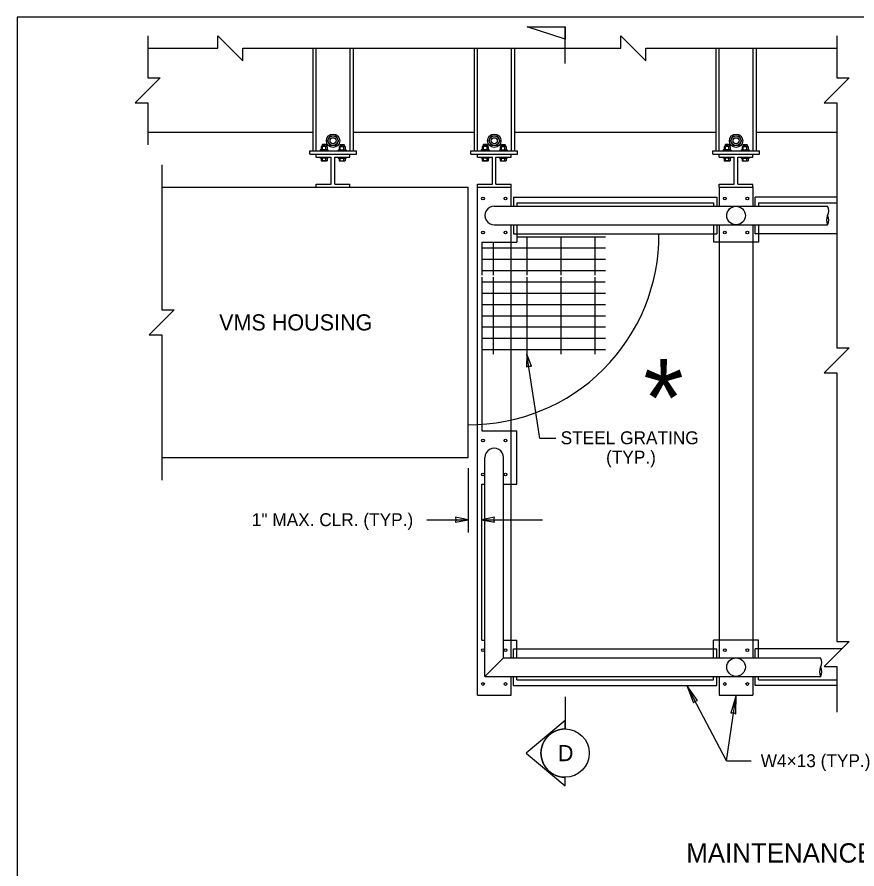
# Model space of a CAD drawing. Extents: x 99862 to 103151, y 100000 to 108076.
# Drawn here: x 99862 to 100904, y 107019 to 108076 of the extents above; entities that cross this region are included whole.
import ezdxf

# ---------------------------------------------------------------- set-up
doc = ezdxf.new("R2010")
doc.units = 0
for name, color, linetype in [('Level 1', 7, 'Continuous'), ('Level 15', 7, 'Continuous'), ('Level 2', 7, 'Continuous'), ('Level 20', 7, 'Continuous'), ('Level 4', 7, 'Continuous'), ('Level 5', 7, 'Continuous'), ('Level 6', 7, 'Continuous'), ('Level 9', 7, 'Continuous')]:
    doc.layers.add(name, color=color, linetype=linetype)

msp = doc.modelspace()

# ---------------------------------------------------------------- linework, layer by layer
at = {"layer": 'Level 1'}
msp.add_lwpolyline([(99862, 105999.5), (103151, 105999.5), (103151, 108075.5), (99862, 108075.5)], close=True, dxfattribs=at)
at = {"layer": 'Level 15'}
for p, q in [((100229.1, 108036.8), (100429.1, 108036.8)), ((100510.6, 107552.9), (100494.7, 107657.5)), ((100530.5, 107552.9), (100510.6, 107552.9)), ((100421.6, 107516), (100421.6, 107436.1)), ((100370.5, 107452.1), (100421.6, 107452.1)), ((100438.7, 107452.1), (100514.1, 107452.1)), ((100742.2, 107153.2), (100693.1, 107246.5)), ((100742.2, 107153.2), (100754.1, 107234.3)), ((100742.2, 107153.2), (100772.7, 107153.2))]:
    msp.add_line(p, q, dxfattribs=at)
for points in [[(100024.1, 108052.2), (100024.1, 108000.2), (100039.6, 108000.2), (100008.6, 107969.2), (100024.1, 107969.2), (100024.1, 107917.1)], [(100024.1, 108036.8), (100111.2, 108036.8), (100111.2, 108052.2), (100142.2, 108021.3), (100142.2, 108036.8), (100229.1, 108036.8)], [(100479.1, 108036.8), (100611, 108036.8), (100611, 108052.2), (100642, 108021.3), (100642, 108036.8), (100729.1, 108036.8)], [(100879.1, 108052.2), (100879.1, 108000.2), (100894.6, 108000.2), (100863.6, 107969.2), (100879.1, 107969.2), (100879.1, 107932.6)], [(100879.1, 107932.6), (100879.1, 107665.2), (100894.6, 107665.2), (100863.6, 107634.3), (100879.1, 107634.3), (100879.1, 107547.2)], [(100041.6, 107892.3), (100041.6, 107712.3), (100057.1, 107712.3), (100026.1, 107681.3), (100041.6, 107681.3), (100041.6, 107501.3)], [(100879.1, 107547.2), (100879.1, 107379.6)], [(100879.1, 107379.6), (100879.1, 107301), (100894.6, 107301), (100863.6, 107270), (100879.1, 107270), (100879.1, 107213.2)]]:
    msp.add_lwpolyline(points, dxfattribs=at)
for points in [[(100494.7, 107657.5), (100494, 107641.5), (100497, 107642.7), (100500.1, 107642.4)], [(100421.6, 107452.1), (100405.9, 107455.2), (100406.6, 107452.1), (100405.9, 107449)], [(100438.7, 107452.1), (100454.4, 107449), (100453.7, 107452.1), (100454.4, 107455.2)], [(100693.1, 107246.5), (100701.1, 107224.9), (100703.2, 107227.2), (100706.4, 107227.7)], [(100754.1, 107234.3), (100747.8, 107212.2), (100750.9, 107212.8), (100753.7, 107211.3)]]:
    msp.add_lwpolyline(points, close=True, dxfattribs=at)
for centre, start, end in [((100857.7, 107835.1), 330, 30), ((100877.7, 107823.5), 150, 210), ((100857.7, 107823.5), 330, 30), ((100849.1, 107275.1), 330, 30), ((100869.1, 107263.5), 150, 210), ((100849.1, 107263.5), 330, 30)]:
    msp.add_arc(centre, 11.5, start, end, dxfattribs=at)
at = {"layer": 'Level 2'}
for p, q in [((100229.1, 108036.8), (100229.1, 107909.6)), ((100229.1, 108036.8), (100279.1, 108036.8)), ((100279.1, 108036.8), (100279.1, 107909.6)), ((100429.1, 108036.8), (100429.1, 107909.6)), ((100429.1, 108036.8), (100479.1, 108036.8)), ((100479.1, 108036.8), (100479.1, 107909.6)), ((100729.1, 108036.8), (100729.1, 107909.6)), ((100729.1, 108036.8), (100879.1, 108036.8)), ((100779.1, 108036.8), (100779.1, 107909.6)), ((100024.1, 107932.6), (100229.1, 107932.6)), ((100279.1, 107932.6), (100429.1, 107932.6)), ((100479.1, 107932.6), (100729.1, 107932.6)), ((100779.1, 107932.6), (100879.1, 107932.6)), ((100225.1, 107909.6), (100283.1, 107909.6)), ((100225.1, 107905.6), (100225.1, 107909.6)), ((100283.1, 107905.6), (100283.1, 107909.6)), ((100425.1, 107909.6), (100483.1, 107909.6)), ((100425.1, 107905.6), (100425.1, 107909.6)), ((100483.1, 107905.6), (100483.1, 107909.6)), ((100725.1, 107909.6), (100783.1, 107909.6)), ((100725.1, 107905.6), (100725.1, 107909.6)), ((100783.1, 107905.6), (100783.1, 107909.6)), ((100225.1, 107905.6), (100283.1, 107905.6)), ((100233.1, 107901.6), (100233.1, 107905.6)), ((100233.1, 107901.6), (100251.9, 107901.6)), ((100251.9, 107868.3), (100251.9, 107901.6)), ((100256.1, 107901.6), (100275.1, 107901.6)), ((100256.1, 107868.3), (100256.1, 107901.6)), ((100275.1, 107901.6), (100275.1, 107905.6)), ((100425.1, 107905.6), (100483.1, 107905.6)), ((100433.1, 107901.6), (100433.1, 107905.6)), ((100433.1, 107901.6), (100452.1, 107901.6)), ((100451.9, 107868.3), (100451.9, 107901.6)), ((100456.1, 107901.6), (100475.1, 107901.6)), ((100456.1, 107868.3), (100456.1, 107901.6)), ((100475.1, 107901.6), (100475.1, 107905.6)), ((100725.1, 107905.6), (100783.1, 107905.6)), ((100733.1, 107901.6), (100733.1, 107905.6)), ((100733.1, 107901.6), (100752.1, 107901.6)), ((100751.9, 107868.3), (100751.9, 107901.6)), ((100756.1, 107901.6), (100775.1, 107901.6)), ((100756.1, 107868.3), (100756.1, 107901.6)), ((100775.1, 107901.6), (100775.1, 107905.6)), ((100233.1, 107864.3), (100233.1, 107868.3)), ((100233.1, 107868.3), (100251.9, 107868.3)), ((100256.1, 107868.3), (100275.1, 107868.3)), ((100275.1, 107864.3), (100275.1, 107868.3)), ((100433.1, 107864.3), (100433.1, 107868.3)), ((100433.1, 107868.3), (100451.9, 107868.3)), ((100456.1, 107868.3), (100475.1, 107868.3)), ((100475.1, 107864.3), (100475.1, 107868.3)), ((100733.1, 107864.3), (100733.1, 107868.3)), ((100733.1, 107868.3), (100751.9, 107868.3)), ((100756.1, 107868.3), (100775.1, 107868.3)), ((100775.1, 107864.3), (100775.1, 107868.3)), ((100041.6, 107864.3), (100421.6, 107864.3)), ((100233.1, 107864.3), (100275.1, 107864.3)), ((100421.6, 107529.3), (100421.6, 107864.3)), ((100433.1, 107864.3), (100475.1, 107864.3)), ((100733.1, 107864.3), (100775.1, 107864.3)), ((100041.6, 107529.3), (100421.6, 107529.3))]:
    msp.add_line(p, q, dxfattribs=at)
for points in [[(100233.1, 107909.6), (100233.1, 108036.8)], [(100275.1, 108036.8), (100275.1, 107909.6)], [(100433.1, 107909.6), (100433.1, 108036.8)], [(100475.1, 108036.8), (100475.1, 107909.6)], [(100733.1, 107909.6), (100733.1, 108036.8)], [(100775.1, 108036.8), (100775.1, 107909.6)]]:
    msp.add_lwpolyline(points, dxfattribs=at)
at = {"layer": 'Level 4'}
for p, q in [((100247.7, 107910.7), (100238, 107910.7)), ((100238, 107910.7), (100238, 107909.6)), ((100247.7, 107909.6), (100238, 107909.6)), ((100239.2, 107914.9), (100239.2, 107910.7)), ((100246.7, 107910.7), (100239.2, 107910.7)), ((100245.9, 107915.1), (100240, 107915.1)), ((100240.4, 107917.1), (100240.9, 107917.4)), ((100240.4, 107917.1), (100240.4, 107915.1)), ((100240.8, 107910.7), (100240.8, 107914.9)), ((100244.9, 107917.4), (100240.9, 107917.4)), ((100244.3, 107916.2), (100241.6, 107916.2)), ((100245.4, 107917.1), (100244.9, 107917.4)), ((100245.1, 107910.7), (100245.1, 107914.9)), ((100245.4, 107917.1), (100245.4, 107915.1)), ((100246.7, 107914.9), (100246.7, 107910.7)), ((100247.7, 107910.7), (100247.7, 107909.6)), ((100260.5, 107910.7), (100270.2, 107910.7)), ((100260.5, 107910.7), (100260.5, 107909.6)), ((100260.5, 107909.6), (100270.2, 107909.6)), ((100261.5, 107914.9), (100261.5, 107910.7)), ((100261.5, 107910.7), (100269, 107910.7)), ((100262.3, 107915.1), (100268.2, 107915.1)), ((100262.8, 107917.1), (100263.3, 107917.4)), ((100262.8, 107917.1), (100262.8, 107915.1)), ((100263.1, 107910.7), (100263.1, 107914.9)), ((100263.3, 107917.4), (100267.3, 107917.4)), ((100263.9, 107916.2), (100266.6, 107916.2)), ((100267.8, 107917.1), (100267.3, 107917.4)), ((100267.4, 107910.7), (100267.4, 107914.9)), ((100267.8, 107917.1), (100267.8, 107915.1)), ((100269, 107914.9), (100269, 107910.7)), ((100270.2, 107910.7), (100270.2, 107909.6)), ((100447.7, 107910.7), (100438, 107910.7)), ((100438, 107910.7), (100438, 107909.6)), ((100447.7, 107909.6), (100438, 107909.6)), ((100439.2, 107914.9), (100439.2, 107910.7)), ((100446.7, 107910.7), (100439.2, 107910.7)), ((100445.9, 107915.1), (100440, 107915.1)), ((100440.4, 107917.1), (100440.9, 107917.4)), ((100440.4, 107917.1), (100440.4, 107915.1)), ((100440.8, 107910.7), (100440.8, 107914.9)), ((100444.9, 107917.4), (100440.9, 107917.4)), ((100444.3, 107916.2), (100441.6, 107916.2)), ((100445.4, 107917.1), (100444.9, 107917.4)), ((100445.1, 107910.7), (100445.1, 107914.9)), ((100445.4, 107917.1), (100445.4, 107915.1)), ((100446.7, 107914.9), (100446.7, 107910.7)), ((100447.7, 107910.7), (100447.7, 107909.6)), ((100460.5, 107910.7), (100470.2, 107910.7)), ((100460.5, 107910.7), (100460.5, 107909.6)), ((100460.5, 107909.6), (100470.2, 107909.6)), ((100461.5, 107914.9), (100461.5, 107910.7)), ((100461.5, 107910.7), (100469, 107910.7)), ((100462.3, 107915.1), (100468.2, 107915.1)), ((100462.8, 107917.1), (100463.3, 107917.4)), ((100462.8, 107917.1), (100462.8, 107915.1)), ((100463.1, 107910.7), (100463.1, 107914.9)), ((100463.3, 107917.4), (100467.3, 107917.4)), ((100463.9, 107916.2), (100466.6, 107916.2)), ((100467.8, 107917.1), (100467.3, 107917.4)), ((100467.4, 107910.7), (100467.4, 107914.9)), ((100467.8, 107917.1), (100467.8, 107915.1)), ((100469, 107914.9), (100469, 107910.7)), ((100470.2, 107910.7), (100470.2, 107909.6)), ((100747.7, 107910.7), (100738, 107910.7)), ((100738, 107910.7), (100738, 107909.6)), ((100747.7, 107909.6), (100738, 107909.6)), ((100739.2, 107914.9), (100739.2, 107910.7)), ((100746.7, 107910.7), (100739.2, 107910.7)), ((100745.9, 107915.1), (100740, 107915.1)), ((100740.4, 107917.1), (100740.9, 107917.4)), ((100740.4, 107917.1), (100740.4, 107915.1)), ((100740.8, 107910.7), (100740.8, 107914.9)), ((100744.9, 107917.4), (100740.9, 107917.4)), ((100744.3, 107916.2), (100741.6, 107916.2)), ((100745.4, 107917.1), (100744.9, 107917.4)), ((100745.1, 107910.7), (100745.1, 107914.9)), ((100745.4, 107917.1), (100745.4, 107915.1)), ((100746.7, 107914.9), (100746.7, 107910.7)), ((100747.7, 107910.7), (100747.7, 107909.6)), ((100760.5, 107910.7), (100770.2, 107910.7)), ((100760.5, 107910.7), (100760.5, 107909.6)), ((100760.5, 107909.6), (100770.2, 107909.6)), ((100761.5, 107914.9), (100761.5, 107910.7)), ((100761.5, 107910.7), (100769, 107910.7)), ((100762.3, 107915.1), (100768.2, 107915.1)), ((100762.8, 107917.1), (100763.3, 107917.4)), ((100762.8, 107917.1), (100762.8, 107915.1)), ((100763.1, 107910.7), (100763.1, 107914.9)), ((100763.3, 107917.4), (100767.3, 107917.4)), ((100763.9, 107916.2), (100766.6, 107916.2)), ((100767.8, 107917.1), (100767.3, 107917.4)), ((100767.4, 107910.7), (100767.4, 107914.9)), ((100767.8, 107917.1), (100767.8, 107915.1)), ((100769, 107914.9), (100769, 107910.7)), ((100770.2, 107910.7), (100770.2, 107909.6)), ((100238, 107901.6), (100238, 107900.4)), ((100247.7, 107900.4), (100238, 107900.4)), ((100239.2, 107900.4), (100239.2, 107897.3)), ((100246.7, 107900.4), (100239.2, 107900.4)), ((100245.9, 107897.1), (100240, 107897.1)), ((100240.8, 107897.3), (100240.8, 107900.4)), ((100245.1, 107897.3), (100245.1, 107900.4)), ((100246.7, 107900.4), (100246.7, 107897.3)), ((100247.7, 107901.6), (100247.7, 107900.4)), ((100260.5, 107901.6), (100260.5, 107900.4)), ((100260.5, 107900.4), (100270.2, 107900.4)), ((100261.5, 107900.4), (100261.5, 107897.3)), ((100261.5, 107900.4), (100269, 107900.4)), ((100262.3, 107897.1), (100268.2, 107897.1)), ((100263.1, 107897.3), (100263.1, 107900.4)), ((100267.4, 107897.3), (100267.4, 107900.4)), ((100269, 107900.4), (100269, 107897.3)), ((100270.2, 107901.6), (100270.2, 107900.4)), ((100438, 107901.6), (100438, 107900.4)), ((100447.7, 107900.4), (100438, 107900.4)), ((100439.2, 107900.4), (100439.2, 107897.3)), ((100446.7, 107900.4), (100439.2, 107900.4)), ((100445.9, 107897.1), (100440, 107897.1)), ((100440.8, 107897.3), (100440.8, 107900.4)), ((100445.1, 107897.3), (100445.1, 107900.4)), ((100446.7, 107900.4), (100446.7, 107897.3)), ((100447.7, 107901.6), (100447.7, 107900.4)), ((100460.5, 107901.6), (100460.5, 107900.4)), ((100460.5, 107900.4), (100470.2, 107900.4)), ((100461.5, 107900.4), (100461.5, 107897.3)), ((100461.5, 107900.4), (100469, 107900.4)), ((100462.3, 107897.1), (100468.2, 107897.1)), ((100463.1, 107897.3), (100463.1, 107900.4)), ((100467.4, 107897.3), (100467.4, 107900.4)), ((100469, 107900.4), (100469, 107897.3)), ((100470.2, 107901.6), (100470.2, 107900.4)), ((100738, 107901.6), (100738, 107900.4)), ((100747.7, 107900.4), (100738, 107900.4)), ((100739.2, 107900.4), (100739.2, 107897.3)), ((100746.7, 107900.4), (100739.2, 107900.4)), ((100745.9, 107897.1), (100740, 107897.1)), ((100740.8, 107897.3), (100740.8, 107900.4)), ((100745.1, 107897.3), (100745.1, 107900.4)), ((100746.7, 107900.4), (100746.7, 107897.3)), ((100747.7, 107901.6), (100747.7, 107900.4)), ((100760.5, 107901.6), (100760.5, 107900.4)), ((100760.5, 107900.4), (100770.2, 107900.4)), ((100761.5, 107900.4), (100761.5, 107897.3)), ((100761.5, 107900.4), (100769, 107900.4)), ((100762.3, 107897.1), (100768.2, 107897.1)), ((100763.1, 107897.3), (100763.1, 107900.4)), ((100767.4, 107897.3), (100767.4, 107900.4)), ((100769, 107900.4), (100769, 107897.3)), ((100770.2, 107901.6), (100770.2, 107900.4)), ((100433.1, 107234.3), (100433.1, 107864.3)), ((100475.1, 107840.8), (100475.1, 107864.3)), ((100733.1, 107864.3), (100733.1, 107840.8)), ((100775.1, 107864.3), (100775.1, 107840.8)), ((100477.9, 107852.1), (100730.3, 107852.1)), ((100477.9, 107852.1), (100477.9, 107840.8)), ((100482.1, 107845.1), (100726.1, 107845.1)), ((100482.1, 107845.1), (100482.1, 107840.8)), ((100726.1, 107845.1), (100726.1, 107840.8)), ((100730.3, 107852.1), (100730.3, 107840.8)), ((100879.1, 107852.1), (100777.9, 107852.1)), ((100777.9, 107840.8), (100777.9, 107852.1)), ((100782.1, 107845.1), (100879.1, 107845.1)), ((100782.1, 107845.1), (100782.1, 107840.8)), ((100475.1, 107280.8), (100475.1, 107817.8)), ((100477.9, 107817.8), (100477.9, 107806.6)), ((100482.1, 107817.8), (100482.1, 107796.1)), ((100726.1, 107817.8), (100726.1, 107796.1)), ((100730.3, 107817.8), (100730.3, 107806.6)), ((100733.1, 107817.8), (100733.1, 107280.8)), ((100775.1, 107817.8), (100775.1, 107280.8)), ((100777.9, 107806.6), (100777.9, 107817.8)), ((100782.1, 107817.8), (100782.1, 107796.1)), ((100477.9, 107806.6), (100730.3, 107806.6)), ((100482.1, 107803.1), (100592.3, 107803.1)), ((100494.7, 107803.1), (100494.7, 107755.5)), ((100536.7, 107803.1), (100536.7, 107755.5)), ((100578.7, 107803.1), (100578.7, 107755.5)), ((100879.1, 107806.6), (100777.9, 107806.6)), ((100438.7, 107796.1), (100482.1, 107796.1)), ((100438.7, 107796.1), (100438.7, 107755.5)), ((100452.7, 107796.1), (100452.7, 107755.5)), ((100782.1, 107796.1), (100726.1, 107796.1)), ((100438.7, 107789.1), (100592.3, 107789.1)), ((100438.7, 107775.1), (100592.3, 107775.1)), ((100438.7, 107761.1), (100592.3, 107761.1)), ((100438.7, 107752.7), (100438.7, 107562.5)), ((100452.7, 107752.7), (100452.7, 107657.5)), ((100494.7, 107752.7), (100494.7, 107657.5)), ((100536.7, 107752.7), (100536.7, 107657.5)), ((100578.7, 107752.7), (100578.7, 107657.5)), ((100438.7, 107747.1), (100591.9, 107747.1)), ((100438.7, 107733.1), (100592.3, 107733.1)), ((100438.7, 107719.1), (100592.3, 107719.1)), ((100438.7, 107705.1), (100592.3, 107705.1)), ((100438.7, 107691.1), (100592.3, 107691.1)), ((100438.7, 107677.1), (100592.3, 107677.1)), ((100438.7, 107663.1), (100592.3, 107663.1)), ((100438.7, 107562.5), (100482.1, 107562.5)), ((100482.1, 107496.1), (100482.1, 107562.5)), ((100438.7, 107302.5), (100438.7, 107496.1)), ((100438.7, 107496.1), (100442.6, 107496.1)), ((100465.6, 107496.1), (100482.1, 107496.1)), ((100438.7, 107302.5), (100442.6, 107302.5)), ((100465.6, 107302.5), (100482.1, 107302.5)), ((100482.1, 107280.8), (100482.1, 107302.5)), ((100782.1, 107302.5), (100726.1, 107302.5)), ((100726.1, 107280.8), (100726.1, 107302.5)), ((100782.1, 107280.8), (100782.1, 107302.5)), ((100477.9, 107292.1), (100730.3, 107292.1)), ((100477.9, 107280.8), (100477.9, 107292.1)), ((100730.3, 107280.8), (100730.3, 107292.1)), ((100777.9, 107280.8), (100777.9, 107292.1)), ((100885.7, 107292.1), (100777.9, 107292.1)), ((100475.1, 107234.3), (100475.1, 107257.8)), ((100477.9, 107246.5), (100477.9, 107257.8)), ((100482.1, 107253.5), (100482.1, 107257.8)), ((100482.1, 107253.5), (100726.1, 107253.5)), ((100726.1, 107253.5), (100726.1, 107257.8)), ((100730.3, 107246.5), (100730.3, 107257.8)), ((100733.1, 107257.8), (100733.1, 107234.3)), ((100775.1, 107257.8), (100775.1, 107234.3)), ((100777.9, 107246.5), (100777.9, 107257.8)), ((100782.1, 107253.5), (100782.1, 107257.8)), ((100782.1, 107253.5), (100879.1, 107253.5)), ((100477.9, 107246.5), (100730.3, 107246.5)), ((100879.1, 107246.5), (100777.9, 107246.5)), ((100433.1, 107234.3), (100475.1, 107234.3)), ((100733.1, 107234.3), (100775.1, 107234.3))]:
    msp.add_line(p, q, dxfattribs=at)
for points in [[(100247.2, 107922.1), (100250.6, 107928.1), (100257.6, 107928.1), (100261, 107922.1), (100257.6, 107916.1), (100250.6, 107916.1)], [(100447.2, 107922.1), (100450.6, 107928.1), (100457.6, 107928.1), (100461, 107922.1), (100457.6, 107916.1), (100450.6, 107916.1)], [(100747.2, 107922.1), (100750.6, 107928.1), (100757.6, 107928.1), (100761, 107922.1), (100757.6, 107916.1), (100750.6, 107916.1)]]:
    msp.add_lwpolyline(points, close=True, dxfattribs=at)
for centre, radius in [((100440.1, 107850.3), 1.68), ((100468.1, 107850.3), 1.68), ((100740.1, 107850.3), 1.68), ((100768.1, 107850.3), 1.68), ((100754.1, 107829.3), 11.5), ((100440.1, 107808.3), 1.68), ((100468.1, 107808.3), 1.68), ((100740.1, 107808.3), 1.68), ((100768.1, 107808.3), 1.68), ((100440.1, 107550.3), 1.68), ((100468.1, 107550.3), 1.68), ((100440.1, 107508.3), 1.68), ((100468.1, 107508.3), 1.68), ((100440.1, 107290.3), 1.68), ((100468.1, 107290.3), 1.68), ((100740.1, 107290.3), 1.68), ((100768.1, 107290.3), 1.68), ((100754.1, 107269.3), 11.5), ((100440.1, 107248.3), 1.68), ((100468.1, 107248.3), 1.68), ((100740.1, 107248.3), 1.68), ((100768.1, 107248.3), 1.68)]:
    msp.add_circle(centre, radius, dxfattribs=at)
for centre, radius, start, end in [((100240, 107913.7), 1.37, 54.7199, 125.2801), ((100242.9, 107905.7), 9.45, 76.7504, 103.2496), ((100245.9, 107913.7), 1.37, 54.7199, 125.2801), ((100262.3, 107913.7), 1.37, 54.7199, 125.2801), ((100265.3, 107905.7), 9.45, 76.7504, 103.2496), ((100268.2, 107913.7), 1.37, 54.7199, 125.2801), ((100440, 107913.7), 1.37, 54.7199, 125.2801), ((100442.9, 107905.7), 9.45, 76.7504, 103.2496), ((100445.9, 107913.7), 1.37, 54.7199, 125.2801), ((100462.3, 107913.7), 1.37, 54.7199, 125.2801), ((100465.3, 107905.7), 9.45, 76.7504, 103.2496), ((100468.2, 107913.7), 1.37, 54.7199, 125.2801), ((100740, 107913.7), 1.37, 54.7199, 125.2801), ((100742.9, 107905.7), 9.45, 76.7504, 103.2496), ((100745.9, 107913.7), 1.37, 54.7199, 125.2801), ((100762.3, 107913.7), 1.37, 54.7199, 125.2801), ((100765.3, 107905.7), 9.45, 76.7504, 103.2496), ((100768.2, 107913.7), 1.37, 54.7199, 125.2801), ((100240, 107898.4), 1.37, 234.7199, 305.2801), ((100242.9, 107906.5), 9.45, 256.7504, 283.2496), ((100245.9, 107898.4), 1.37, 234.7199, 305.2801), ((100262.3, 107898.4), 1.37, 234.7199, 305.2801), ((100265.3, 107906.5), 9.45, 256.7504, 283.2496), ((100268.2, 107898.4), 1.37, 234.7199, 305.2801), ((100440, 107898.4), 1.37, 234.7199, 305.2801), ((100442.9, 107906.5), 9.45, 256.7504, 283.2496), ((100445.9, 107898.4), 1.37, 234.7199, 305.2801), ((100462.3, 107898.4), 1.37, 234.7199, 305.2801), ((100465.3, 107906.5), 9.45, 256.7504, 283.2496), ((100468.2, 107898.4), 1.37, 234.7199, 305.2801), ((100740, 107898.4), 1.37, 234.7199, 305.2801), ((100742.9, 107906.5), 9.45, 256.7504, 283.2496), ((100745.9, 107898.4), 1.37, 234.7199, 305.2801), ((100762.3, 107898.4), 1.37, 234.7199, 305.2801), ((100765.3, 107906.5), 9.45, 256.7504, 283.2496), ((100768.2, 107898.4), 1.37, 234.7199, 305.2801), ((100454.1, 107829.3), 11.5, 89.9981, 270.0019), ((100454.1, 107529.3), 11.5, 359.989, 180)]:
    msp.add_arc(centre, radius, start, end, dxfattribs=at)
at = {"layer": 'Level 5'}
for p, q in [((100454.1, 107840.8), (100867.7, 107840.8)), ((100454.1, 107817.8), (100867.7, 107817.8)), ((100442.6, 107257.8), (100442.6, 107529.3)), ((100465.6, 107280.8), (100465.6, 107529.3)), ((100465.6, 107280.8), (100442.6, 107257.8)), ((100465.6, 107280.8), (100859.1, 107280.8)), ((100442.6, 107257.8), (100859.1, 107257.8))]:
    msp.add_line(p, q, dxfattribs=at)
msp.add_arc((100423.4, 107804.8), 235, 269.5597, 0.423, dxfattribs=at)
at = {"layer": 'Level 6'}
for centre, radius in [((100254.1, 107922.1), 8.34), ((100454.1, 107922.1), 8.34), ((100754.1, 107922.1), 8.34), ((100254.1, 107922.1), 5.99), ((100254.1, 107922.1), 3.75), ((100454.1, 107922.1), 5.99), ((100454.1, 107922.1), 3.75), ((100754.1, 107922.1), 5.99), ((100754.1, 107922.1), 3.75)]:
    msp.add_circle(centre, radius, dxfattribs=at)
at = {"layer": 'Level 9'}
for p, q in [((100542, 108018), (100542, 108063.5)), ((100542, 107232.6), (100542, 107192.6)), ((100542, 107203.2), (100493.5, 107162.6)), ((100542, 107192.6), (100542, 107203.2)), ((100493.5, 107162.6), (100542, 107122)), ((100542, 107122), (100542, 107132.6))]:
    msp.add_line(p, q, dxfattribs=at)
msp.add_lwpolyline([(100542, 108048), (100495.1, 108063.5), (100542, 108063.5)], close=True, dxfattribs=at)
msp.add_circle((100542, 107162.6), 30, dxfattribs=at)
msp.add_arc((100542, 107162.6), 30, 89.9978, 270.0022, dxfattribs=at)

# ---------------------------------------------------------------- texts
at = {"layer": 'Level 20'}
for s, height, p in [('VMS HOUSING', 20, (100112.7, 107686.8)), ('*', 96, (100639.1, 107555.4)), ('STEEL GRATING', 16, (100536.5, 107545.7)), ('(TYP.)', 16, (100592.8, 107521.7)), ('1" MAX. CLR. (TYP.)', 16, (100153.3, 107444.1)), ('D', 20, (100533, 107152.6)), ('W4×13 (TYP.)', 16, (100784.7, 107145.2)), ('MAINTENANCE WALKWAY', 24, (100692.3, 107026.8))]:
    msp.add_text(s, height=height, dxfattribs=at).set_placement(p)

doc.saveas('drawing.dxf')
